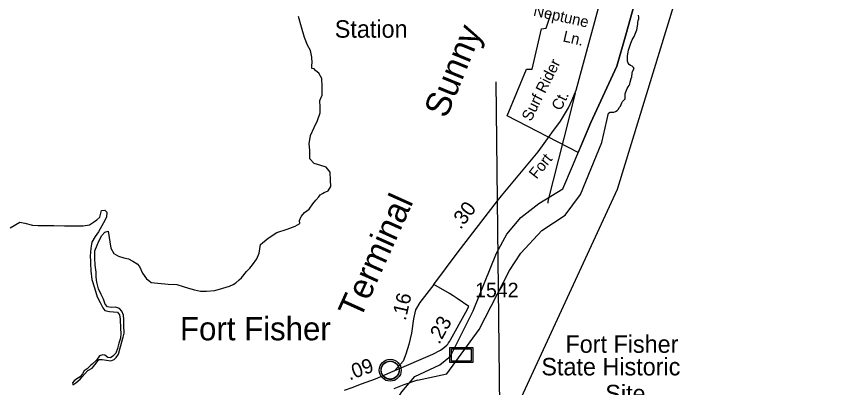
# Model space of a CAD drawing. Extents: x 2290055 to 2389491, y 66597 to 237875.
# Drawn here: x 2324371 to 2331474, y 81050 to 84234 of the extents above; entities that cross this region are included whole.
import ezdxf

# ---------------------------------------------------------------- set-up
doc = ezdxf.new("R2010")
doc.units = 0
for name, color, linetype in [('Exist Aviation Commercial or Municipal Label', 7, 'Continuous'), ('Exist Boundary Land Use Reservation Military US Department of Defense Label', 7, 'Continuous'), ('Exist Boundary Political City Limit New', 7, 'Continuous'), ('Exist Boundary Political CountyLine', 7, 'Continuous'), ('Exist Civil Demographics City Label', 7, 'Continuous'), ('Exist Civil Demographics Community CELL', 7, 'Continuous'), ('Exist Cultural Educational Facility Middle Label', 7, 'Continuous'), ('Exist Cultural Historical Site CELL', 7, 'Continuous'), ('Exist Hydrographic Island Shore', 7, 'Continuous'), ('Exist Road Non-System Type 51', 7, 'Continuous'), ('Exist Road Non-System Type 51 Label', 7, 'Continuous'), ('Exist Road Primary US Attributed', 7, 'Continuous'), ('Exist Road Primary US Label', 7, 'Continuous'), ('Exist Road Primary US Mileage Hundredths English Label', 7, 'Continuous'), ('Exist Road Secondary Mileage Hundredths English Label', 7, 'Continuous'), ('Exist Road Secondary Type 51 Attributed', 7, 'Continuous'), ('Exist Road Secondary Type 51 Number Label', 7, 'Continuous'), ('Map Preparation Boundary City Limit Buffer Line', 7, 'Continuous'), ('Map Preparation Inset Cut Line', 7, 'Continuous'), ('Map Preparation Longitude Latitude Lines', 7, 'Continuous')]:
    doc.layers.add(name, color=color, linetype=linetype)

msp = doc.modelspace()

# ---------------------------------------------------------------- linework, layer by layer
at = {"layer": 'Exist Boundary Political City Limit New'}
msp.add_lwpolyline([(2329781, 84734.6), (2329599.2, 84075.6), (2329521.8, 83807.2), (2329298.2, 83324.2), (2329190.2, 83067.6), (2328580, 83380.7), (2328747, 83782.7), (2328795.5, 83782.7), (2328876, 84128.8), (2328915, 84133.7), (2328954, 84254.3)], dxfattribs=at)
at = {"layer": 'Exist Boundary Political CountyLine'}
msp.add_lwpolyline([(2325835.3, 75452), (2326172, 76975.8), (2326499.8, 78183.4), (2327256.8, 80136.5), (2327355.1, 80434.7), (2327480.3, 80697.1), (2327677, 81013.2), (2327787.3, 81144.4), (2328001.8, 81242.8), (2328094.2, 81317.4), (2328287.9, 81708), (2328487.6, 82203), (2328577, 82367), (2328696.2, 82510.1), (2328851.1, 82629.4), (2329056.8, 82754.6), (2329140.2, 82948.5), (2329298.2, 83324.2), (2329521.7, 83807.2), (2329599.2, 84075.6), (2329780.9, 84734.6), (2330069.9, 85774.1), (2330486.3, 87434.7), (2331265, 90397.2)], dxfattribs=at)
at = {"layer": 'Exist Civil Demographics Community CELL'}
msp.add_lwpolyline([(2327499.1, 81210.3), (2327500.1, 81215.8), (2327501.8, 81222.4), (2327504.8, 81229.6), (2327507.7, 81235.4), (2327511, 81241.1), (2327514.8, 81246.2), (2327518.7, 81250.6), (2327523.3, 81255.2), (2327528.9, 81259.8), (2327534.3, 81263.4), (2327539.2, 81266.3), (2327544.2, 81268.7), (2327549.7, 81271), (2327555.3, 81272.9), (2327559.6, 81274), (2327564.5, 81274.7), (2327568.6, 81275.5), (2327575, 81275.7), (2327579.4, 81275.6), (2327585.1, 81275.4), (2327590, 81274.6), (2327594.9, 81273.7), (2327599.9, 81272.2), (2327605.1, 81270.3), (2327611.7, 81267.4), (2327618, 81263.9), (2327623, 81260.3), (2327628.2, 81256.3), (2327631.5, 81253.2), (2327635.6, 81248.8), (2327639.5, 81244.1), (2327642.6, 81239.5), (2327645.7, 81234.5), (2327648.2, 81229.4), (2327650.2, 81224.3), (2327651.8, 81219.3), (2327653, 81214.7), (2327654.1, 81208.7), (2327654.8, 81204), (2327655, 81198), (2327654.8, 81192.2), (2327654.3, 81186.5), (2327653.3, 81181), (2327651.7, 81174.9), (2327649.8, 81169), (2327647.5, 81164), (2327644.4, 81158), (2327641.1, 81152.7), (2327637.6, 81148), (2327633.4, 81143.2), (2327628.1, 81138.2), (2327623.1, 81134.1), (2327618.1, 81130.7), (2327613.8, 81128.2), (2327606.9, 81124.9), (2327599.8, 81122.2), (2327593.8, 81120.8), (2327587.2, 81119.5), (2327582.8, 81119), (2327578.3, 81118.7), (2327572.7, 81118.7), (2327568.5, 81119.2), (2327562.8, 81119.9), (2327556.9, 81121.2), (2327552.3, 81122.5), (2327547.1, 81124.4), (2327542.6, 81126.4), (2327538.6, 81128.6), (2327531.8, 81132.7), (2327526.3, 81136.9), (2327521.3, 81141.4), (2327516.9, 81146.3), (2327513.7, 81150.3), (2327510.7, 81154.4), (2327506.6, 81161.5), (2327504.9, 81165.1), (2327503.2, 81169.1), (2327500.6, 81177.3), (2327499.1, 81184.3), (2327498.4, 81189.5), (2327498, 81195.8), (2327498, 81200.5), (2327498.5, 81207)], close=True, dxfattribs=at)
for centre, radius in [((2327576.7, 81197.8), 94.3), ((2327576.4, 81198.1), 76.7)]:
    msp.add_circle(centre, radius, dxfattribs=at)
at = {"layer": 'Exist Cultural Historical Site CELL'}
for points in [[(2328088.8, 81394.2), (2328284.9, 81394.2), (2328284.9, 81262.7), (2328088.8, 81262.7)], [(2328102.7, 81380.3), (2328271, 81380.3), (2328271, 81276.6), (2328102.7, 81276.6)]]:
    msp.add_lwpolyline(points, close=True, dxfattribs=at)
at = {"layer": 'Exist Hydrographic Island Shore'}
for points in [[(2327810.5, 81111.7), (2328062, 81167.5), (2328339.9, 81548.1), (2328599.7, 82052.5), (2328696.3, 82203.6), (2328877.6, 82396.9), (2329077, 82529.8), (2329209.9, 82705), (2329391.1, 83152.1), (2329450.5, 83404.7), (2329463.7, 83412.4), (2329479.2, 83414.2), (2329495.2, 83414.2), (2329510, 83418.2), (2329524, 83426.5), (2329534.2, 83438.6), (2329541.7, 83451.6), (2329551.2, 83464.8), (2329558.7, 83477.9), (2329562.7, 83493.4), (2329569.2, 83505.4), (2329581, 83515.3), (2329591.5, 83526.1), (2329593.7, 83541), (2329591.2, 83556), (2329593.5, 83571.5), (2329598.5, 83586.9), (2329609.7, 83616.6), (2329617.7, 83630.1), (2329627.7, 83641.4), (2329634, 83654.6), (2329634.7, 83670.2), (2329643.5, 83700.6), (2329649.2, 83715.7), (2329652, 83747.1), (2329656.5, 83762.3), (2329670.2, 83787.4), (2329664.5, 83797.4), (2329653, 83807), (2329639, 83812.9), (2329625.7, 83821.5), (2329617.7, 83834.9), (2329612.5, 83850), (2329612, 83866.4), (2329613.5, 83896.7), (2329619.5, 83928.1), (2329621.7, 83944.1), (2329641.7, 84004.5), (2329648, 84019), (2329653.5, 84034.4), (2329670.7, 84061.2), (2329693, 84120.9), (2329700.5, 84168.5), (2329701.7, 84183.7), (2329704.2, 84199.1), (2329708.7, 84214.6), (2329710.2, 84229.7), (2329706.5, 84245.4)], [(2326936.6, 83770), (2326924.5, 83785.5), (2326905.4, 83788.9), (2326905.2, 83816.4), (2326908.1, 83837.5), (2326905.4, 83884.5), (2326892.1, 83940.9), (2326867.7, 83987.7), (2326841, 84053.4), (2326815.8, 84143), (2326788.9, 84234.7)], [(2326995.2, 82714.1), (2327010.6, 82722.5), (2327045.3, 82737.3), (2327066.6, 82775.1), (2327064.7, 82828.7), (2327062.7, 82898.2), (2327027.4, 82939.9), (2326982.5, 82954), (2326923, 82972.3), (2326886.5, 83012.6), (2326887.6, 83085.7), (2326881, 83140), (2326891.5, 83212.5), (2326925.1, 83280.1), (2326953.6, 83341.8), (2326975.9, 83407.2), (2326974.9, 83457.1), (2326973.1, 83512.2), (2326993.6, 83558.7), (2326993, 83632.5), (2326990.3, 83702), (2326965.3, 83748.1), (2326939, 83766.7), (2326936.6, 83770)], [(2326816.2, 82520.4), (2326842.5, 82550.3), (2326882.6, 82581), (2326911.6, 82626.1), (2326938.8, 82658.2), (2326963, 82686.7), (2326975.9, 82703.4), (2326995.2, 82714.1)], [(2324317.2, 82420.3), (2324399.5, 82468.1), (2324441.5, 82459.7), (2324507.5, 82444.3), (2324557.6, 82438.9), (2324620.5, 82439.5), (2324690, 82439.3), (2324781.3, 82438.6), (2324869, 82436.4), (2324941.2, 82437), (2324996.2, 82444.7), (2325031, 82469.6), (2325060.6, 82487.9), (2325083.9, 82512), (2325092.5, 82545.4), (2325099.5, 82568.6), (2325127, 82571), (2325145.2, 82555.2), (2325142, 82511.1)], [(2325142, 82511.1), (2325117.8, 82462.3), (2325073.5, 82385.2), (2325045, 82345.9), (2325017.7, 82297.9), (2325008.7, 82246.4), (2325002.7, 82176.1), (2325003.8, 82132.8)], [(2326279.8, 81972.4), (2326300.9, 81991.2), (2326342.7, 82045.1), (2326373.5, 82073.6), (2326394.4, 82103.5), (2326431.5, 82153), (2326452.2, 82203.9), (2326465.2, 82276.4), (2326530.8, 82330.5), (2326604.2, 82380.3), (2326692.2, 82410), (2326761.1, 82434.5), (2326802.1, 82457.3), (2326798.2, 82483.3), (2326812.5, 82516), (2326816.2, 82520.4)], [(2325292.7, 81514.5), (2325294.3, 81522.5), (2325292.3, 81576.8), (2325291, 81631.8), (2325289.6, 81669.5), (2325273, 81705.5), (2325253.5, 81727.1), (2325219.3, 81739.1), (2325183, 81737.4), (2325151.2, 81742.2), (2325131.5, 81765.2), (2325115.9, 81808.5), (2325096.9, 81848.9), (2325074.5, 81896.5), (2325058.3, 81952.8), (2325055, 81997.7), (2325054, 82039), (2325044.8, 82099.7), (2325041.5, 82157.6), (2325043.7, 82223.5), (2325063.4, 82271.5), (2325076.6, 82306.3), (2325103.4, 82352.9), (2325128.4, 82383.5), (2325157.8, 82392)], [(2325157.8, 82392), (2325178.3, 82244.2), (2325205.9, 82199.5), (2325245.5, 82178.1), (2325289.8, 82161.1), (2325331, 82152.7), (2325369.6, 82134.2), (2325406.7, 82112.1), (2325424.9, 82089.1), (2325452.2, 82032.1), (2325484.4, 81981.7), (2325504.9, 81968.8), (2325525.2, 81951.6), (2325581.8, 81944.8), (2325671, 81935.4), (2325744.8, 81934.6), (2325800, 81917.6), (2325847.3, 81903.5), (2325897.2, 81886.6), (2325950.3, 81875.4), (2326001.5, 81875.8), (2326072.5, 81880.8), (2326141.8, 81903), (2326197.6, 81918), (2326230.6, 81934.2), (2326251.5, 81947.4), (2326279.8, 81972.4)], [(2325003.8, 82132.8), (2325004, 82113.9), (2325006.8, 82051.6), (2325016.1, 81975.7), (2325039, 81904.2), (2325061.6, 81829.1), (2325088.4, 81777.9), (2325107.9, 81739.8)], [(2325107.9, 81739.8), (2325110.8, 81734.6), (2325128.2, 81710.9), (2325169, 81702.5), (2325203.7, 81699.9), (2325235.5, 81696.5), (2325254.5, 81672.1), (2325259.3, 81636.6), (2325261.9, 81554.8), (2325266.8, 81513.6), (2325263.6, 81472.3), (2325247.2, 81428.7), (2325237.5, 81385.2), (2325223.2, 81343.1), (2325196.1, 81319.7), (2325176.4, 81304.3), (2325154.7, 81307), (2325128.4, 81325.7), (2325109.8, 81330.6), (2325081.5, 81320.2), (2325055.8, 81284.5), (2325020, 81250.4)], [(2325239, 81325.9), (2325246.5, 81336), (2325259, 81390.4), (2325286.5, 81480.4), (2325292.7, 81514.5)], [(2324934.4, 81141.8), (2324956.8, 81165.7), (2324982, 81194.9), (2325018.7, 81215.4), (2325041.5, 81244.6), (2325063, 81270.8), (2325077.6, 81289.8), (2325105.1, 81290.7), (2325179.1, 81278.3), (2325207, 81289.4), (2325225, 81306.9), (2325239, 81325.9)], [(2325020, 81250.4), (2325009.1, 81240), (2324976.1, 81208.6), (2324951.5, 81193.2), (2324936.5, 81167), (2324916.4, 81140), (2324888.9, 81124.6), (2324863.9, 81106.3), (2324851.8, 81088.1), (2324852.2, 81078.7)], [(2324852.2, 81078.7), (2324852.4, 81072.9), (2324878.5, 81088.3), (2324915.2, 81121.2), (2324934.4, 81141.8)], [(2327810.5, 81111.7), (2327694.2, 81073.1), (2327607.7, 81037)]]:
    msp.add_lwpolyline(points, dxfattribs=at)
at = {"layer": 'Exist Road Non-System Type 51'}
msp.add_line((2329163.5, 83576.2), (2329066, 83190.2), dxfattribs=at)
msp.add_lwpolyline([(2329066, 83190.2), (2328929.2, 82648.6), (2328927.9, 82632.5)], dxfattribs=at)
at = {"layer": 'Exist Road Primary US Attributed'}
for points in [[(2327952.4, 81933.8), (2328152.2, 82202.8), (2328497.2, 82652.1), (2328530.6, 82695.6), (2328846.2, 83073.7), (2328964.1, 83235.7), (2329037.1, 83335.9), (2329106.3, 83450.9), (2329139.2, 83518.2), (2329173.6, 83602), (2329432.1, 84563.6), (2329558.1, 85055.5), (2329833.9, 86081.2), (2330002.8, 86725.4), (2330119.5, 87164.9), (2330280.1, 87784.4), (2330359, 88081.7), (2330479.2, 88534.3)], [(2327952.4, 81933.8), (2327830.8, 81778.4), (2327792.7, 81716.1), (2327775.4, 81639.8), (2327758, 81515.1), (2327737.2, 81418), (2327709.5, 81334.8), (2327688.7, 81275.9), (2327616.7, 81196.6)], [(2327185.6, 81026.8), (2327250.6, 81050.1), (2327330.2, 81080.3), (2327449.2, 81124.2), (2327524.3, 81154.4), (2327581.9, 81180.1), (2327616.7, 81196.6)]]:
    msp.add_lwpolyline(points, dxfattribs=at)
at = {"layer": 'Exist Road Secondary Type 51 Attributed'}
for points in [[(2328088.1, 81447.9), (2328093.5, 81459.4), (2328225.6, 81697.5), (2328252.4, 81745.1), (2328150.8, 81812.4), (2328116.4, 81835.7), (2328084.6, 81855.7), (2327952.4, 81933.8)], [(2327616.7, 81196.6), (2327943.5, 81335.7), (2328008, 81370.1), (2328028.6, 81383.8), (2328046.4, 81397.6), (2328063.8, 81412.3), (2328072.2, 81422.2), (2328077.9, 81431.8), (2328088.1, 81447.9)]]:
    msp.add_lwpolyline(points, dxfattribs=at)
at = {"layer": 'Map Preparation Boundary City Limit Buffer Line'}
msp.add_lwpolyline([(2329781, 84734.6), (2329599.2, 84075.6), (2329521.8, 83807.2), (2329298.2, 83324.2), (2329190.2, 83067.6), (2328580, 83380.7), (2328747, 83782.7), (2328795.5, 83782.7), (2328876, 84128.8), (2328915, 84133.7), (2328954, 84254.3)], dxfattribs=at)
at = {"layer": 'Map Preparation Inset Cut Line'}
msp.add_lwpolyline([(2327293.1, 115381.1), (2326421, 108601.1), (2323940.9, 84753.9), (2319662, 79548.4), (2319961.8, 76608.6), (2326693.5, 76608.6), (2329528, 82750.7), (2336452.5, 105360.7), (2339748.2, 115381.1)], close=True, dxfattribs=at)
at = {"layer": 'Map Preparation Longitude Latitude Lines'}
msp.add_line((2328632.5, 70256.5), (2328486, 83673.2), dxfattribs=at)

# ---------------------------------------------------------------- texts
at = {"layer": 'Exist Aviation Commercial or Municipal Label'}
msp.add_text('Station', height=150, dxfattribs=at).set_placement((2327101.1, 84052))
at = {"layer": 'Exist Boundary Land Use Reservation Military US Department of Defense Label'}
for s, rotation, p in [('Sunny', 67.75935, (2328059.1, 83352.2)), ('Terminal', 65.70441, (2327318.8, 81628))]:
    msp.add_text(s, height=215, rotation=rotation, dxfattribs=at).set_placement(p)
at = {"layer": 'Exist Civil Demographics City Label'}
msp.add_text('Fort Fisher', height=200, dxfattribs=at).set_placement((2325773.4, 81454.5))
at = {"layer": 'Exist Cultural Educational Facility Middle Label'}
for s, p in [('Fort Fisher', (2329080.1, 81347.3)), ('State Historic', (2328873.6, 81153.3)), ('Site', (2329422.1, 80922.5))]:
    msp.add_text(s, height=150, dxfattribs=at).set_placement(p)
at = {"layer": 'Exist Road Non-System Type 51 Label'}
for s, rotation, p in [('Neptune', 347.58189, (2328799.4, 84242)), ('Ln.', 346.79577, (2329052.4, 84021.7)), ('Surf Rider', 63.34346, (2328784.1, 83328.2)), ('Ct.', 63.34346, (2329039.9, 83419.3))]:
    msp.add_text(s, height=95, rotation=rotation, dxfattribs=at).set_placement(p)
at = {"layer": 'Exist Road Primary US Label'}
msp.add_text('Fort', height=95, rotation=51.54001, dxfattribs=at).set_placement((2328832.5, 82832.7))
at = {"layer": 'Exist Road Primary US Mileage Hundredths English Label'}
for s, rotation, p in [('.30', 52.48166, (2328180.1, 82399.9)), ('.16', 77.19573, (2327709.4, 81618.4)), ('.09', 20.27375, (2327227.6, 81109))]:
    msp.add_text(s, height=125, rotation=rotation, dxfattribs=at).set_placement(p)
at = {"layer": 'Exist Road Secondary Mileage Hundredths English Label'}
msp.add_text('.23', height=125, rotation=60.98481, dxfattribs=at).set_placement((2327996.8, 81413.9))
at = {"layer": 'Exist Road Secondary Type 51 Number Label'}
msp.add_text('1542', height=125, dxfattribs=at).set_placement((2328305.6, 81823.8))

doc.saveas('drawing.dxf')
